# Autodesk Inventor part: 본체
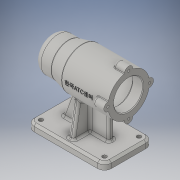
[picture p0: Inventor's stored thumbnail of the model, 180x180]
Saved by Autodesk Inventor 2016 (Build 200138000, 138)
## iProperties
Created: 2019-07
Part Number: 본체
Material: 일반
Document SubType Name: Modeling
Designer: 605-01
Density: 1 g/cm^3
Appearance: 기본값
Author: 605-01
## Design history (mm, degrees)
sketch "스케치1"
  geometry: L1 (0, 0)-(-112, 0); L2 (0, 0)-(0, 15); L3 (-10, 25)-(-25, 25); L4 (-25, 25)-(-45, 30); L5 (-45, 30)-(-112, 30); L6 (-112, 30)-(-112, 22); L7 (-111, 21)-(-97, 21); L8 (-97, 21)-(-97, 21); L9 (-94, 24)-(-52, 24); L10 (-49, 21)-(-49, 21); L11 (-49, 21)-(-37.3, 21); L12 (-37, 20.7)-(-37, 17.5); L13 (-37, 17.5)-(-19.3, 17.5); L14 (-19, 17.2)-(-19, 16); L15 (-19, 16)-(-15.3, 16); L16 (-15, 15.7)-(-15, 10.5); L17 (-15, 10.5)-(-15, 10.5); L18 (-12, 7.5)-(-12, 0); L19 (-112, 21)-(-112, 0); L20 (-111, 21)-(-112, 22); A1 r 3 centre (-15, 7.5) between (-12, 7.5) and (-15, 10.5); A2 r 0.3 centre (-15.3, 15.7) between (-15, 15.7) and (-15.3, 16); A3 r 0.3 centre (-19.3, 17.2) between (-19, 17.2) and (-19.3, 17.5); A4 r 0.3 centre (-37.3, 20.7) between (-37, 20.7) and (-37.3, 21); A5 r 3 centre (-52, 21) between (-49, 21) and (-52, 24); A6 r 3 centre (-94, 21) between (-94, 24) and (-97, 21); A7 r 10 centre (-10, 15) between (0, 15) and (-10, 25); 1 further point
  constraints: 40 end point, 14 point on circle, 14 tangent, 12 perpendicular, 7 centre point, 7 point on line, 3 equal radius, 3 horizontal, 2 vertical
  dimensions: "d0" = 50 diameter of L3 L1; "d1" = 60 diameter of L4.end L1; "d2" = 25 distance from line of L3.end L2; "d3" = 45 distance from line of L4.end L2; "d4" = 112 distance between parallel lines of L6 L2; "d5" = 42 diameter of L7 L1; "d6" = 15 distance between parallel lines of L8 L6; "d7" = 48 distance between parallel lines of L10 L8; "d8" = 48 diameter of L9 L1; "d9" = 12 distance between parallel lines of L10 L12; "d10" = 18 distance between parallel lines of L12 L14; "d11" = 35 diameter of L13 L1; "d12" = 32 diameter of L15 L1; "d13" = 3 distance between parallel lines of L16 L18; "d14" = 21 diameter of L17 L1; "d15" = 4 distance between parallel lines of L14 L16; "d16" = 3 radius of A1; "d17" = 0.3 radius of A2; "d18" = 3 radius of A5; "d19" = 1 distance of L7.start L19.start; "d20" = 1 distance of L6.end L19.start (= d19); "d21" = 10 radius of A7
revolve "회전1" sketch "스케치1" stored, may be unused: angle "d22" = 90 deg
sketch "스케치2" dims "d23" = 60
  geometry: C1 r 10.5 at (0, 0) reference; C2 r 6 at (-30, 0); C3 r 6 at (0, -30); C4 r 6 at (30, 0); C5 r 6 at (0, 30); 2 further points
  constraints: 4 centre point, 2 horizontal alignment, 1 coincident, 11 other
  dimensions: "d24" = 12 diameter of C2; "d27" = 360 deg dimension on point (0, 0) C2.centre (derived)
extrude "돌출1" join sketch "스케치2" distance "d29" = 16; taper "d30" = 0 deg
sketch "스케치3" dims "d31" = 60
  geometry: C1 r 7.5 at (30, 0) reference; 6 further points
  constraints: 2 horizontal alignment, 1 coincident, 7 other
  dimensions: "d34" = 360 deg dimension on point (30, 0) point (0, 0) (derived)
hole "구멍1" sketch "스케치3" at (0, 0), (30, -30), (60, 0), (30, 30) diameter "d36" = 3.242; stored, may be unused: countersink angle "d40" = 90 deg, drill point angle "d42" = 118 deg; dims "d37" = 8, "d38" = 4, "d39" = 2, "d41" = 11
node "작업 평면1"
sketch "스케치4"
  geometry: L1 (10, 35)-(102, 35); L2 (112, 25)-(112, -25); L3 (102, -35)-(10, -35); L4 (0, -25)-(0, 25); L5 (0, 0)-(-12.604, 0); A1 r 10 centre (10, 25) between (10, 35) and (0, 25); A2 r 10 centre (10, -25) between (0, -25) and (10, -35); A3 r 10 centre (102, -25) between (102, -35) and (112, -25); A4 r 10 centre (102, 25) between (112, 25) and (102, 35)
  constraints: 10 end point, 8 point on circle, 8 tangent, 4 centre point, 3 equal radius, 2 horizontal, 2 parallel, 1 midpoint, 1 perpendicular, 1 other
  dimensions: "d44" = 112 distance between parallel lines of L2 L4; "d45" = 70 distance between parallel lines of L3 L1; "d46" = 10 radius of A1
extrude "돌출2" join sketch "스케치4" distance "d47" = 10; taper "d48" = 0 deg
sketch "스케치5"
  geometry: A1 r 10 centre (10, 25) between (10, 35) and (0, 25) reference; A2 r 10 centre (10, -25) between (0, -25) and (10, -35) reference; A3 r 10 centre (102, -25) between (102, -35) and (112, -25) reference; A4 r 10 centre (102, 25) between (112, 25) and (102, 35) reference; 5 further points
  constraints: 4 coincident
hole "구멍2" sketch "스케치5" at (10, 25), (10, -25), (102, -25), (102, 25) diameter "d49" = 6; stored, may be unused: countersink angle "d53" = 90 deg, drill point angle "d55" = 118 deg; dims "d50" = 8, "d51" = 4, "d52" = 2, "d54" = 6
node "작업 평면2"
sketch "스케치6"
  geometry: L1 (-25, -70)-(-35, -70) reference; L2 (-28, -70)-(-19.654, -22.666); L3 (35, -70)-(25, -70) reference; L4 (28, -70)-(19.654, -22.666); L5 (-35, -80)-(-35, -70) reference; L6 (35, -80)-(35, -70) reference; L7 (-28, -70)-(-22, -70) reference; L8 (-28, -70)-(28, -70); L9 (28, -80)-(28, -70) reference; A1 r 30 centre (0, 0) between (-19.654, -22.666) and (19.654, -22.666) reference; A2 r 30 centre (0, 0) between (-19.654, -22.666) and (19.654, -22.666); 1 further point
  constraints: 6 end point, 4 point on circle, 2 point on line, 1 centre point, 1 coincident, 1 perpendicular
  dimensions: "d57" = 7 distance from line of L5 L2.start; "d58" = 7 distance from line of L6 L4.start; "d59" = 100 deg angle of L3 L4; "d60" = 100 deg angle of L1 L2
extrude "돌출3" join sketch "스케치6" stored distance "d61" = 8; taper "d62" = 0 deg
sketch "스케치7"
  geometry: L1 (56, 4)-(87, 4); L2 (87, 4)-(87, -4); L3 (87, -4)-(56, -4); L4 (56, -4)-(56, 4); L5 (0, 0)-(-6.742, 0); L6 (112, -25)-(112, 25) reference
  constraints: 10 end point, 2 horizontal, 2 parallel, 1 perpendicular, 1 other
  dimensions: "d63" = 8 distance between parallel lines of L3 L1; "d64" = 56 distance between parallel lines of L6 L4; "d65" = 25 distance between parallel lines of L6 L2
extrude "돌출4" join sketch "스케치7" stored distance "d66" = 8; taper "d67" = 0 deg
sketch "스케치8"
  geometry: L1 (-102, -70)-(-10, -70) reference; L2 (-20, -70)-(-29.796, -43.086); L3 (0, -80)-(0, -70) reference; 1 further point
  constraints: 2 end point, 1 point on line
  dimensions: "d70" = 20 distance from line of L3 L2.start; "d71" = 110 deg angle of L1 L2
feature "리브1" sketch "스케치8" dims "d72" = 1, "d73" = 8, "d74" = 0, "d75" = 0, "d76" = 1, "d77" = 1
chamfer "모따기1" distance "d78" = 3; stored, may be unused: second distance "d79" = 2, angle "d80" = 45 deg
fillet "모깎기1" dims "d81" = 3
fillet "모깎기2" dims "d82" = 3
fillet "모깎기3" dims "d83" = 3
node "작업 평면3"
sketch "스케치9"
  geometry: L1 (33.5, 29.4)-(33.5, 5.97) reference; 2 further points
  constraints: 1 horizontal alignment, 1 other
  dimensions: "d84" = 42 distance from line of L1 point (-8.5, 0)
feature "엠보싱1" sketch "스케치9" dims "d0" = 50, "d1" = 60, "d2" = 25, "d3" = 45, "d4" = 112, "d5" = 42, "d6" = 15, "d7" = 48, "d8" = 48, "d9" = 12, "d10" = 18, "d11" = 35, "d12" = 32, "d13" = 3, "d14" = 21, "d15" = 4, "d16" = 3, "d17" = 0.3, "d18" = 3, "d19" = 1, "d20" = 1 (= d19), "d21" = 10, "d85" = 0.5, "d86" = 0
fillet "모깎기4" dims "d87" = 3
fillet "모깎기5" dims "d88" = 1
node "솔리드1"
other parameters: "d56" = 56
